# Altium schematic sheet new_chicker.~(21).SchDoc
size A4
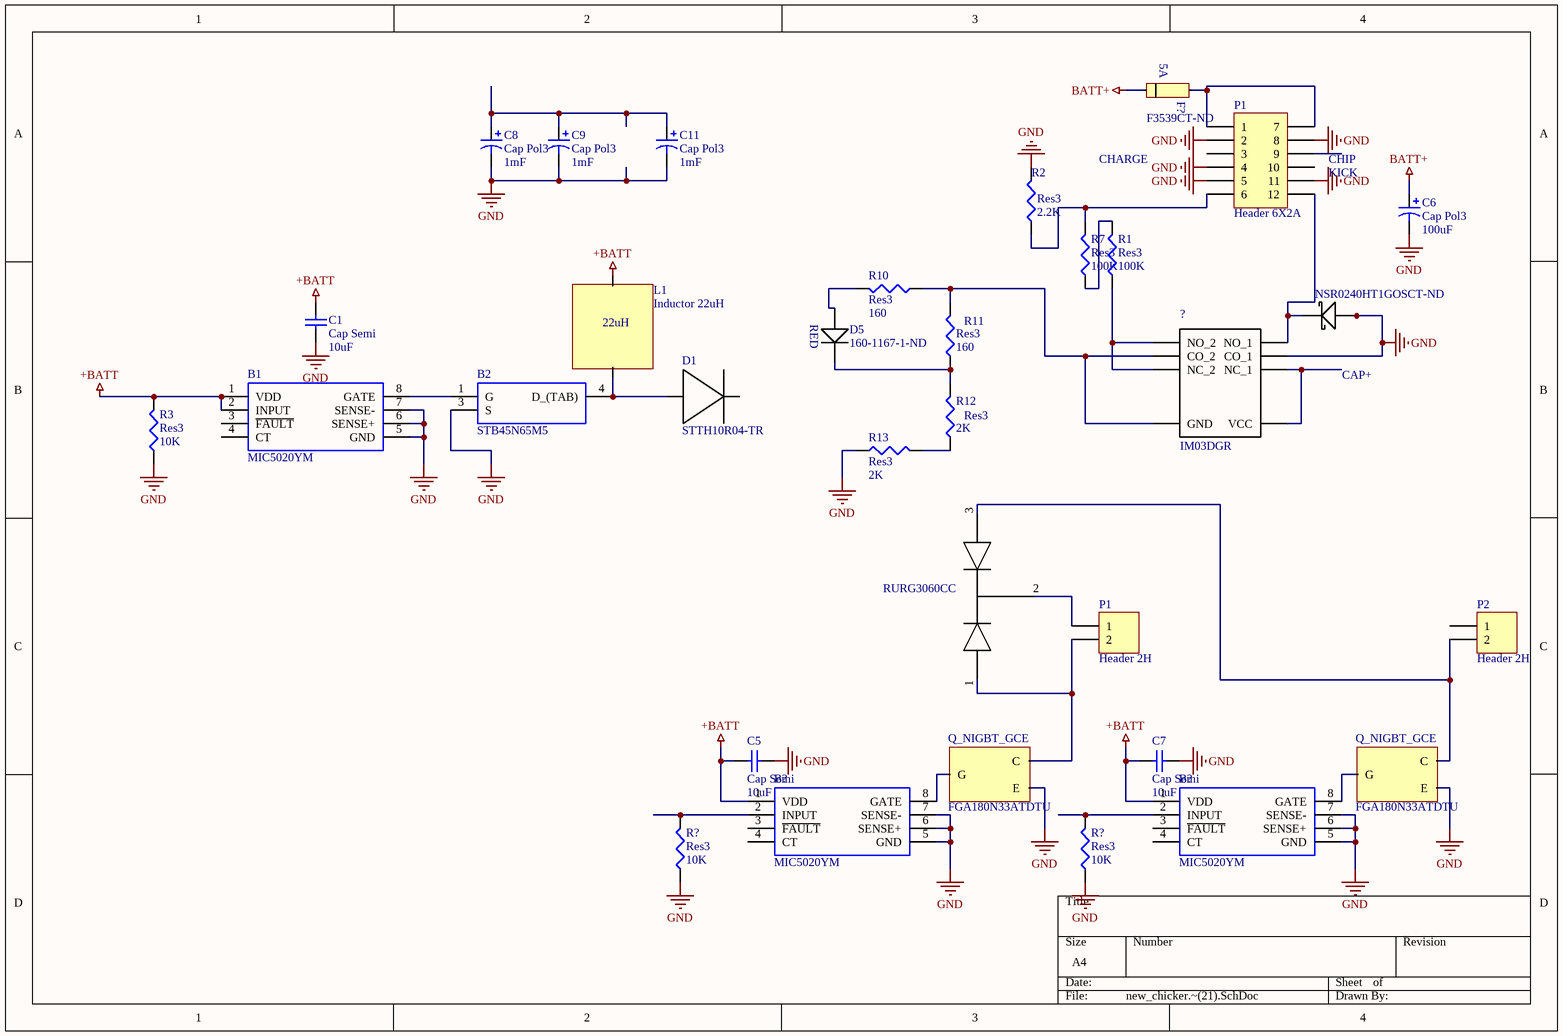
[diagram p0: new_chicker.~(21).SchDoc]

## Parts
(Parts that share a designator on the sheet are numbered #1, #2 ... from top to bottom, then left to right.)
1  NSR0240HT1GOSCT-ND  [SOD2512X110N]
?  IM03DGR  [GULLWINGS]
B1  MIC5020YM  [SOIC127P600X188-8N]
B2  STB45N65M5  [TO254P1542X460-3N]
B?#1  MIC5020YM  [SOIC127P600X188-8N]
B?#2  MIC5020YM  [SOIC127P600X188-8N]
C1  Cap Semi  value 10uF  [C1206]
C5  Cap Semi  value 10uF  [C1206]
C6  Cap Pol3  value 100uF  [C0805]
C7  Cap Semi  value 10uF  [C1206]
C8  Cap Pol3  value 1mF  [C0805]
C9  Cap Pol3  value 1mF  [C0805]
C11  Cap Pol3  value 1mF  [C0805]
D1#1  STTH10R04-TR  [STTH10R04G-TR]
D1#2  RURG3060CC  [TO-247]  (value not drawn)
D5  160-1167-1-ND  [1206-C]
F1  F3539CT-ND  [1206-C]
L1  Inductor 22uH  [PCBComponent_1]
P1#1  Header 6X2A  [HDR2X6_CEN]
P1#2  Header 2H  [HDR1X2H]
P2  Header 2H  [HDR1X2H]
Q1  FGA180N33ATDTU  [TO-247]
Q2  FGA180N33ATDTU  [TO-247]
R1  Res3  value 100K  [J1-0603]
R2  Res3  value 2.2K  [J1-0603]
R3  Res3  value 10K  [J1-0603]
R7  Res3  value 100K  [J1-0603]
R10  Res3  value 160  [J1-0603]
R11  Res3  value 160  [J1-0603]
R12  Res3  value 2K  [J1-0603]
R13  Res3  value 2K  [J1-0603]
R?#1  Res3  value 10K  [J1-0603]
R?#2  Res3  value 10K  [J1-0603]

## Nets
+BATT: B1.1(VDD) B1.2(INPUT) B?#1.1(VDD) B?#2.1(VDD) C1.2 C5.1 C7.1 L1.1 R3.2
BATT+: C6.1 F1.10
GND: 1.12 ?.3(CO_1) B1.5(GND) B1.6(SENSE+) B1.7(SENSE-) B2.3(S) B?#1.5(GND) B?#1.6(SENSE+) B?#1.7(SENSE-) B?#2.5(GND) B?#2.6(SENSE+) B?#2.7(SENSE-) C1.1 C5.2 C6.2 C7.2 C8.2 C9.2 C11.2 P1#1.2 P1#1.4 P1#1.5 P1#1.8 P1#1.11 Q1.3(E) Q2.3(E) R2.2 R3.1 R13.1 R?#1.1 R?#2.1
Net1_11: 1.11 ?.4(NO_1) P1#1.12
Net?_1: ?.1(VCC) ?.2(NC_1)
Net?_5: ?.5(NO_2) ?.7(NC_2) R1.1
Net?_6: ?.6(CO_2) ?.8(GND) R10.1 R11.2
NetB1_8: B1.8(GATE) B2.1(G)
NetB2_4: B2.4(D_(TAB)) D1#1.0 L1.0
NetB?#1_2: B?#1.2(INPUT) R?#1.2
NetB?#1_8: B?#1.8(GATE) Q1.G
NetB?#2_2: B?#2.2(INPUT) R?#2.2
NetB?#2_8: B?#2.8(GATE) Q2.G
NetC8_1: C8.1 C9.1 C11.1
NetD1#2_1: D1#2.1 P1#2.2 Q1.4(C)
NetD1#2_2: D1#2.2 P1#2.1
NetD1#2_3: D1#2.3 P2.2 Q2.4(C)
NetD5_13: D5.13 R10.2
NetD5_14: D5.14 R11.1 R12.2
NetF1_9: F1.9 P1#1.1 P1#1.7
NetP1#1_6: P1#1.6 R2.1 R7.2
NetR1_2: R1.2 R7.1
NetR12_1: R12.1 R13.2

Not connected (* = marked no-connect by the designer): B1 3(~{FAULT}) 4(CT); B?#1 3(~{FAULT}) 4(CT); B?#2 3(~{FAULT}) 4(CT); D1#1 1; P1#1 3 9 10; P2 1

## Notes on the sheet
- CHARGE
- (near P1#1) CHIP
- KICK
- CAP+

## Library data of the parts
? = IM03DGR: Relay, Signal, Dpdt, 250vac, 220vdc, 5a; MF: TE Connectivity
B1 B?#1 B?#2 = MIC5020YM: MICROCHIP - MIC5020YM - IC, DRIVER, MOSFET, LOW SIDE; Geometry.Height: 1.879mm
B2 = STB45N65M5: Manufacturer_Name: STMicroelectronics; Allied_Number: 70390681; Geometry.Height: 4.6mm
C1 C5 C7 = Cap Semi: Capacitor (Semiconductor SIM Model)
C6 C8 C9 C11 = Cap Pol3: Polarized Capacitor (Surface Mount)
P1#1 = Header 6X2A: Header, 6-Pin, Dual row
P1#2 P2 = Header 2H: Header, 2-Pin, Right Angle
R1-R3 R7 R10-R13 R?#1 R?#2 = Res3: Resistor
